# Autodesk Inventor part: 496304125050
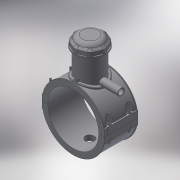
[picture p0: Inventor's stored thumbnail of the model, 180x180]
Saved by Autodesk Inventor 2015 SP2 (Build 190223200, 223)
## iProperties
Created: 2017-07
Part Number: 496304125050
Material: Generic
Description: PLASSON TAPPING SADDLE 125x50
Document SubType Name: Modeling
Designer: KIM
Mass: 946.994 g
Surface Area: 2107.25 cm^2
Volume: 946.994 cm^3
Density: 1 g/cm^3
Appearance: Default
Author: KIM
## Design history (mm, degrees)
derived "496304.ipt"
feature "Solid1::496304.ipt"
feature "Solid2::496304.ipt"
feature "Solid4::496304.ipt"
feature "Solid5::496304.ipt"
tag "TaggingFeature1"
body "Solid1"
body "Solid2"
other parameters: "d0" = 125, "d2" = 162, "d3" = 31.25, "d4" = 118, "d5" = 0, "d6" = 0.1, "d8" = 0, "d19" = 6, "d20" = 6, "d21" = 70.8, "d23" = 0, "d24" = 35.4, "d26" = 0, "d29" = 3, "d30" = 41.66667, "d31" = 6, "d32" = 0, "d33" = 0, "d34" = 0.6, "d40" = 78, "d41" = 62.5, "d43" = 0, "d45" = 0, "d47" = 145.8, "d70" = 15, "d72" = 0, "d73" = 6, "d75" = 5, "d76" = 0, "d77" = 6.25, "d78" = 92.5, "d79" = 15, "d80" = 47.2, "d82" = 5 deg, "d84" = 4, "d85" = 14, "d86" = 0, "d87" = 3, "d88" = 0, "d89" = 1, "d90" = 1, "d91" = 94.4, "d92" = 0, "d93" = 0.5, "d94" = 65.78947, "d96" = 153, "d97" = 2.36, "d98" = 0, "d102" = 1.25, "d120" = 140 deg, "d121" = 24.228, "d122" = 20 deg, "d126" = 0, "d143" = 128.75, "d145" = 19.23077, "d149" = 1.875, "d150" = 21.15385, "d153" = 118, "d154" = 0, "d156" = 75, "d157" = 160 deg, "d159" = 5, "d161" = 1.875, "d162" = 70.8, "d163" = 0, "d164" = 62.5, "d167" = 12.5, "d168" = 73.17073, "d170" = 3.375, "d172" = 0, "d173" = 1, "d175" = 62.5, "d176" = 20 deg, "d177" = 8.75, "d178" = 25, "d180" = 0, "d184" = 7, "d185" = 38.35, "d186" = 38.35, "d187" = 75, "d188" = 7.5, "d189" = 8.75, "d190" = 0, "d191" = 112.5, "d193" = 6.3, "d194" = 4.13, "d195" = 90 deg, "d197" = 0, "d199" = 0, "d200" = 12.5, "d202" = 0, "d203" = 177, "d204" = 59.375, "d205" = 43.75, "d206" = 53.125, "d207" = 132.75, "d208" = 138.06, "d209" = 164.61, "d210" = 53.75, "d211" = 62.5, "d213" = 35.1, "d216" = 0, "d217" = 12.5, "d218" = 12.5, "d219" = 2.5, "d222" = 125, "d224" = 0, "d230" = 5, "d233" = 6, "d236" = 81, "d237" = 35.4, "d238" = 6.02433, "d240" = 35.4, "d241" = 35.4, "d242" = 35.4, "d243" = 6, "d244" = 35.4, "d245" = 35.4, "d246" = 35.4, "d247" = 6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
